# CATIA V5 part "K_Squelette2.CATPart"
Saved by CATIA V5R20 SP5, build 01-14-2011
Part number: squelette2
Publications: "Point.10", "Droite.4", "Droite.5", "Point.11", "Droite.6", "Point.12", "Droite.7", "Point.13", "Point.14", "Droite.8", "Point.15", "Point.16", "Droite.9", "Point.17", "Point.18", "Point.19", "Droite.10", "Point.20", "Plan.1", "Point.21", "Plan.2", "Plan.3", "Plan.4", "Plan.5", "Plan.6", "Plan.7", "Plan.8", "Plan.9", "Plan.10", "Plan.11", "Plan.12", "Plan.13", "Plan.14", "Plan.15", "Plan.16", "Plan.17", "Plan.18", "Plan.19", "Point.23", "Plan.21"
Bounding box of the stored display mesh (mm): x -29.991 to 29.991, y -226 to 226, z -29.992 to 529.992
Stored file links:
  G:\Khaled_CFAO_2011\ST2M\ST2M_GR1\lpierredon\Khaled\CAD_thinkMOTION\K_Squelette2.CATPart
  J:\think_motion\squelette .CATPart
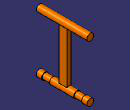
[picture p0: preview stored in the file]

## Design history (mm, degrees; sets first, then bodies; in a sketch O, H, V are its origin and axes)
Parameters
  demi_longueur_axe = 226 mm
  longueur_support_pied_verticale = 175 mm
  longueur_entraxe = 685 mm
  longueur_support_pied_horizontale = 683 mm
  distance_axe_pivot = 65 mm
  hauteur_axe_pivot = 39 mm
  demi_distance_entre_2supports_pieds = 142.5 mm
  rainure = 5 mm
Set1 "chassis_stepper"
  Point1 "origine_stepper": type OnPlane, Support yz-plane, H 0, V 0, Direction (0, 1, 0)
  Point2: type OnPlane, Support yz-plane, H 225, V 0, Direction (0, 1, 0)
  Point3: type OnPlane, Support yz-plane, H -225, V 0, Direction (0, 1, 0)
  Line1 "axe_avant": type PtPt, FirstPoint Point3, SecondPoint Point2
  Point4: type OnPlane, Support yz-plane, H 0, V 500, Direction (0, 1, 0)
  Line2: type PtPt, FirstPoint Point4, SecondPoint Point1
  Point5: type OnPlane, Support yz-plane, H 225, V 500, Direction (0, 1, 0)
  Point6: type OnPlane, Support yz-plane, H -225, V 500, Direction (0, 1, 0)
  Line3: type PtPt, FirstPoint Point6, SecondPoint Point5
  Point7: (0, -142.5, 0)
  Point8: (0, 142.5, 0)
  Point9: type OnPlane, Support xy-plane, H 200, V -142.5, Direction (1, 0, 0)
  Point10: type OnPlane, Support xy-plane, H 200, V 142.5, Direction (1, 0, 0)
  Line4: type PtPt, FirstPoint Point9, SecondPoint Point7
  Line5: type PtPt, FirstPoint Point10, SecondPoint Point8
  Point11: (200, -142.5, 500)
  Line6 "longueur_support": type PtPt, FirstPoint Point9, SecondPoint Point11
  Point12: (200, 142.5, 500)
  Line7: type PtPt, FirstPoint Point10, SecondPoint Point12
  Point13 "Point": type OnPlane, Support zx-plane, H -172.069, V 46.692, Direction (-1, 0, 0)
  Point14: type OnPlane, Support yz-plane, H 0, V 46.692, Direction (0, 1, 0)
  Line8: type PtPt, FirstPoint Point13, SecondPoint Point14
  Point15: (39, 35, 47.174)
  Point16: (39, -35, 47.174)
  Line9: type PtPt, FirstPoint Point16, SecondPoint Point15
  Point17: (39, 0, 46.692)
  Point18: (60, 0, 135)
  Point19: (60, 0, 0)
  Line10: type PtPt, FirstPoint Point18, SecondPoint Point19
  Point20: (101.09, 0, 135)
  Plane1: type Normal, Curve Line8, RefPoint Point20
  Point21: (60, 0, 135)
  Plane2: type OffsetPt, RefPlane zx-plane, RefPoint Point3
  Plane3: type OffsetPt, RefPlane zx-plane, RefPoint Point2
  Plane4: type OffsetPt, RefPlane xy-plane, RefPoint Point4
  Plane5: type OffsetPt, RefPlane zx-plane, RefPoint Point4
  Plane6: type OffsetPt, RefPlane Plane5, RefPoint Point5
  Plane7: type OffsetPt, RefPlane Plane5, RefPoint Point6
  Plane8: type OffsetPt, RefPlane yz-plane, RefPoint Point14
  Plane9: type OffsetPt, RefPlane Plane8, RefPoint Point13
  Plane10: type OffsetPt, RefPlane Plane9, RefPoint Point10
  Plane11: type OffsetPt, RefPlane Plane9, RefPoint Point9
  Plane12: type OffsetPt, RefPlane xy-plane, RefPoint Point19
  Plane13: type OffsetPt, RefPlane Plane12, RefPoint Point18
  Plane14: type OffsetPt, RefPlane zx-plane, RefPoint Point16
  Plane15: type OffsetPt, RefPlane zx-plane, RefPoint Point15
  Plane16: type OffsetPt, RefPlane Plane13, RefPoint Point11
  Plane17: type OffsetPt, RefPlane Plane16, RefPoint Point12
  Plane18: type Offset, RefPlane Plane12, Offset -22.5
  Sketch1 on xy-plane, origin (0, 0, 0), H (1, 0, 0), V (0, 1, 0)
    point P1 (0, 226)
    line L1 (0, 226) -> (30, 226)
    line L2 (30, 226) -> (30, 177.5)
    line L3 (30, 177.5) -> (25, 177.5)
    line L4 (25, 177.5) -> (25, 107.5)
    line L5 (25, 107.5) -> (30, 107.5)
    point P6 (30, 107.5)
    line L6 (30, 107.5) -> (30, -107.5)
    line L7 (30, -107.5) -> (25, -107.5)
    point P8 (25, -107.5)
    line L8 (25, -107.5) -> (25, -177.5)
    line L9 (25, -177.5) -> (30, -177.5)
    point P10 (30, -177.5)
    line L10 (30, -177.5) -> (30, -226)
    line L11 (30, -226) -> (0, -226)
    point P12 (0, -226)
    reference projected line E1 (200, 142.5) -> (0, 142.5) from Line5
    reference projected line E2 (200, -142.5) -> (0, -142.5) from Line4
    reference projected line E3 (172.069, 0) -> (0, 0) from Line8
    length L4 = 70
    length L8 = 70
    length L3 = 5
    length L1 = 30
    coincidence: P1 V, P6 L2, P8 L4, P10 L2, P12 V
    horizontal: L1 H, L3 H, L5 H, L7 H, L9 H, L11 H
    vertical: L2 V, L4 V, L6 V, L8 V, L10 V
    symmetry: L3 L5 E1, L7 L9 E2, L1 L11 E3
    parallelism: L1 L11
  Point22: (154.73, 0, 135)
  Plane19: type OffsetPt, RefPlane Plane1, RefPoint Point22
  Point23: (134.5, 0, 46.692)
  Plane20: type OffsetPt, RefPlane Plane9, RefPoint Point23
Body1 (main body)
  Shaft1: profile Sketch1, axis Line1, angle 360
  Sketch2 on xy-plane, origin (0, 0, 0), H (1, 0, 0), V (0, 1, 0)
    line L1 (-17.5, 35) -> (17.5, 35)
    line L2 (17.5, 35) -> (17.5, -35)
    line L3 (17.5, -35) -> (-17.5, -35)
    line L4 (-17.5, -35) -> (-17.5, 35)
    length L2 = 70
    length L3 = 35
    horizontal: L1 H, L3 H
    vertical: L2 V, L4 V
    symmetry: L2 L4 V, L1 L3 H
  Pad1: profile Sketch2, direction (0, 0, 1), up to Plane4
  Sketch3 on Plane4, origin (0, 0, 500), H (1, 0, 0), V (0, 1, 0)
    point P1 (0, 225)
    line L1 (0, 225) -> (30, 225)
    line L2 (30, 225) -> (30, -225)
    line L3 (30, -225) -> (0, -225)
    point P4 (0, -225)
    length L2 = 450
    length L3 = 30
    coincidence: P1 V, P4 V
    horizontal: L1 H, L3 H
    vertical: L2 V
    symmetry: L3 L1 H
  Shaft2: profile Sketch3, axis Line3, angle 360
